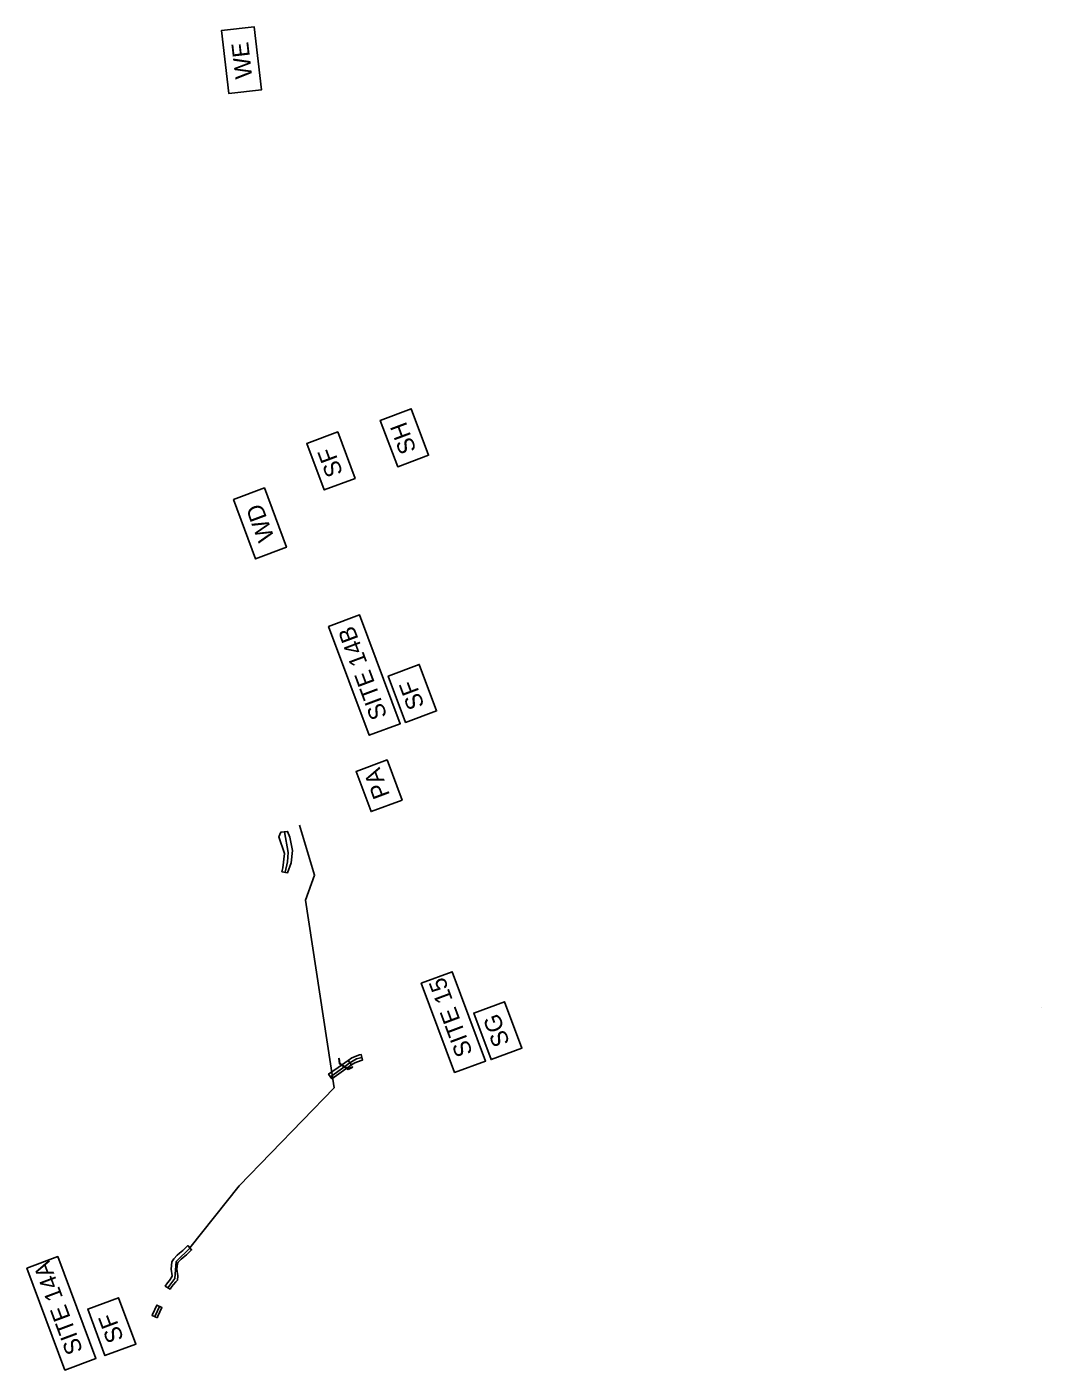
# Model space of a CAD drawing. Extents: x 474218 to 481634, y 484357 to 504997.
# Drawn here: x 478263 to 479157, y 494616 to 495800 of the extents above; entities that cross this region are included whole.
import ezdxf

# ---------------------------------------------------------------- set-up
doc = ezdxf.new("R2010")
doc.units = 0
for name, color, linetype in [('Exist Hydro Jurisdictional Stream or Body of Water', 7, 'Continuous'), ('Old_Level_29', 7, 'Continuous'), ('Old_Level_30', 7, 'Continuous'), ('Prop Earthen Structure Impacts In Surface Waters Hatching CELL', 7, 'Continuous'), ('Prop Grid Mask', 7, 'Continuous'), ('Scratch_Level_4', 7, 'Continuous'), ('Temp Earthen Structure Impacts In Surface Waters Hatching CELL', 7, 'Continuous')]:
    doc.layers.add(name, color=color, linetype=linetype)

msp = doc.modelspace()

# ---------------------------------------------------------------- linework, layer by layer
at = {"layer": 'Exist Hydro Jurisdictional Stream or Body of Water'}
for points in [[(478589.5, 495412.3), (478574.2, 495453.2), (478601.4, 495463.4), (478616.7, 495422.4)], [(478524.7, 495391.9), (478509.4, 495432.9), (478536.7, 495443.1), (478552, 495402.1)], [(478596.5, 495186.8), (478581.2, 495227.8), (478608.5, 495238), (478623.8, 495197)], [(478566.1, 495108.2), (478552.9, 495143.6), (478580.1, 495153.8), (478593.3, 495118.4)], [(478671.8, 494889.5), (478656.5, 494930.5), (478683.7, 494940.6), (478699, 494899.7)], [(478331.5, 494628.5), (478316.3, 494669.5), (478343.5, 494679.6), (478358.8, 494638.7)]]:
    msp.add_lwpolyline(points, close=True, dxfattribs=at)
at = {"layer": 'Old_Level_29'}
for points in [[(478564.4, 495175.5), (478528.6, 495271.4), (478555.9, 495281.6), (478591.7, 495185.7)], [(478639.7, 494878.2), (478610.3, 494956.8), (478637.6, 494967), (478666.9, 494888.3)], [(478296.2, 494615.7), (478262.7, 494705.6), (478289.9, 494715.8), (478323.5, 494625.9)]]:
    msp.add_lwpolyline(points, close=True, dxfattribs=at)
at = {"layer": 'Old_Level_30'}
for points in [[(478440.6, 495741.5), (478434.2, 495796.9), (478463.1, 495800.2), (478469.5, 495744.8)], [(478464.3, 495331.1), (478444.8, 495383.4), (478472, 495393.6), (478491.5, 495341.3)]]:
    msp.add_lwpolyline(points, close=True, dxfattribs=at)
at = {"layer": 'Prop Earthen Structure Impacts In Surface Waters Hatching CELL'}
for points in [[(478487.5, 495055.2), (478492.4, 495054.3), (478495.6, 495063.1), (478496.7, 495074), (478494.4, 495085.6), (478492.4, 495090.7), (478486.6, 495090.2), (478484.8, 495086), (478489.6, 495071.2), (478488.2, 495058.6), (478487.5, 495055.2)], [(478539.8, 494878.6), (478548.9, 494884.8), (478545.8, 494888.8), (478536.9, 494882.7), (478528.6, 494876.8), (478531.5, 494872.7), (478539.8, 494878.6)]]:
    msp.add_lwpolyline(points, dxfattribs=at)
at = {"layer": 'Prop Grid Mask'}
for points in [[(478469.5, 495744.8), (478463.1, 495800.2), (478434.2, 495796.9), (478440.6, 495741.5)], [(478616.7, 495422.4), (478601.4, 495463.4), (478574.2, 495453.2), (478589.5, 495412.3)], [(478552, 495402.1), (478536.7, 495443.1), (478509.4, 495432.9), (478524.7, 495391.9)], [(478491.5, 495341.3), (478472, 495393.6), (478444.8, 495383.4), (478464.3, 495331.1)], [(478591.7, 495185.7), (478555.9, 495281.6), (478528.6, 495271.4), (478564.4, 495175.5)], [(478623.8, 495197), (478608.5, 495238), (478581.2, 495227.8), (478596.5, 495186.8)], [(478593.3, 495118.4), (478580.1, 495153.8), (478552.9, 495143.6), (478566.1, 495108.2)], [(478666.9, 494888.3), (478637.6, 494967), (478610.3, 494956.8), (478639.7, 494878.2)], [(478699, 494899.7), (478683.7, 494940.6), (478656.5, 494930.5), (478671.8, 494889.5)], [(478323.5, 494625.9), (478289.9, 494715.8), (478262.7, 494705.6), (478296.2, 494615.7)], [(478358.8, 494638.7), (478343.5, 494679.6), (478316.3, 494669.5), (478331.5, 494628.5)]]:
    msp.add_lwpolyline(points, close=True, dxfattribs=at)
at = {"layer": 'Scratch_Level_4'}
for p, q in [((478486.6, 495090.2), (478492.4, 495090.7)), ((478492.4, 495054.3), (478487.5, 495055.2)), ((479156.6, 494935.1), (479156.6, 494935.1)), ((478538, 494890.5), (478537.5, 494890.9)), ((478537.5, 494890.9), (478538.1, 494885.7)), ((478538.6, 494886), (478538, 494890.5)), ((478547.2, 494886.6), (478530.2, 494874.4)), ((478538.1, 494885.7), (478545.8, 494880.9)), ((478545.8, 494881.4), (478538.6, 494886)), ((478549.6, 494883.2), (478545.8, 494881.4)), ((478545.8, 494880.9), (478550.1, 494882.8)), ((478550.1, 494882.8), (478549.6, 494883.2))]:
    msp.add_line(p, q, dxfattribs=at)
for points in [[(478502.9, 495096.4), (478516.3, 495052.1), (478508.3, 495030), (478533.5, 494864.6), (478449.9, 494778.2), (478406.2, 494723.7), (478406.2, 494723.7), (478406.2, 494723.7)], [(478487.5, 495055.2), (478488.2, 495058.6), (478489.6, 495071.2), (478484.8, 495086), (478486.6, 495090.2)], [(478490.2, 495054.7), (478492.4, 495064), (478492.9, 495072.3), (478489.6, 495090.4)], [(478492.4, 495090.7), (478494.4, 495085.6), (478496.7, 495074), (478495.6, 495063.1), (478492.4, 495054.3)], [(478547.2, 494886.6), (478553.1, 494890.2), (478558, 494891.3)], [(478387, 494688.4), (478393.1, 494696.6), (478394.3, 494711.4), (478406.5, 494723.7)], [(478375.6, 494662.8), (478375.9, 494664.2), (478379.6, 494671.9)]]:
    msp.add_lwpolyline(points, dxfattribs=at)
msp.add_lwpolyline([(478377.7, 494661.8), (478378, 494663.3), (478381.7, 494670.9), (478377.2, 494673.1), (478373.3, 494664.9), (478373.1, 494664)], close=True, dxfattribs=at)
at = {"layer": 'Temp Earthen Structure Impacts In Surface Waters Hatching CELL'}
msp.add_line((478545.8, 494888.8), (478548.9, 494884.8), dxfattribs=at)
for points in [[(478548.9, 494884.8), (478550.2, 494885.7), (478551.7, 494886.8), (478557.2, 494888.9), (478558.5, 494889.1), (478557.4, 494894), (478555.9, 494893.8), (478549.1, 494891), (478545.8, 494888.8)], [(478400.5, 494715.1), (478403.3, 494717.5), (478407.9, 494721.8), (478404.5, 494725.5), (478400, 494721.2), (478397.1, 494718.8), (478395.2, 494717.1), (478392.1, 494713.9), (478390.5, 494711.2), (478389.8, 494704.8), (478390.7, 494698.9), (478390.5, 494698.1), (478388.3, 494694.7), (478386.5, 494692.6), (478384.7, 494689.9), (478388.9, 494687.2), (478390.4, 494689.5), (478392, 494691.3), (478394.1, 494693.6), (478395.3, 494695), (478395.7, 494698.8), (478394.9, 494704.9), (478395.4, 494709.7), (478396.1, 494710.9), (478398.6, 494713.5), (478400.5, 494715.1)], [(478377.7, 494661.8), (478378, 494663.3), (478381.7, 494670.9), (478377.2, 494673.1), (478373.3, 494664.9), (478373.1, 494664), (478377.7, 494661.8)]]:
    msp.add_lwpolyline(points, dxfattribs=at)

# ---------------------------------------------------------------- texts
at = {"layer": 'Exist Hydro Jurisdictional Stream or Body of Water'}
for s, p in [('SH', (478606.2, 495426.9)), ('SF', (478541.5, 495406.6)), ('SF', (478613.3, 495201.5)), ('PA', (478582.8, 495122.9)), ('SG', (478688.5, 494904.2)), ('SF', (478348.3, 494643.2))]:
    msp.add_text(s, height=15, rotation=110.4693, dxfattribs=at).set_placement(p)
at = {"layer": 'Old_Level_29'}
for s, p in [('SITE 14B', (478580.5, 495192.6)), ('SITE 15', (478655.8, 494895.3)), ('SITE 14A', (478312.3, 494632.8))]:
    msp.add_text(s, height=15, rotation=110.4693, dxfattribs=at).set_placement(p)
at = {"layer": 'Old_Level_30'}
for s, rotation, p in [('WE', 96.5776, (478461.4, 495755.3)), ('WD', 110.4693, (478481.1, 495349.6))]:
    msp.add_text(s, height=15, rotation=rotation, dxfattribs=at).set_placement(p)

doc.saveas('drawing.dxf')
